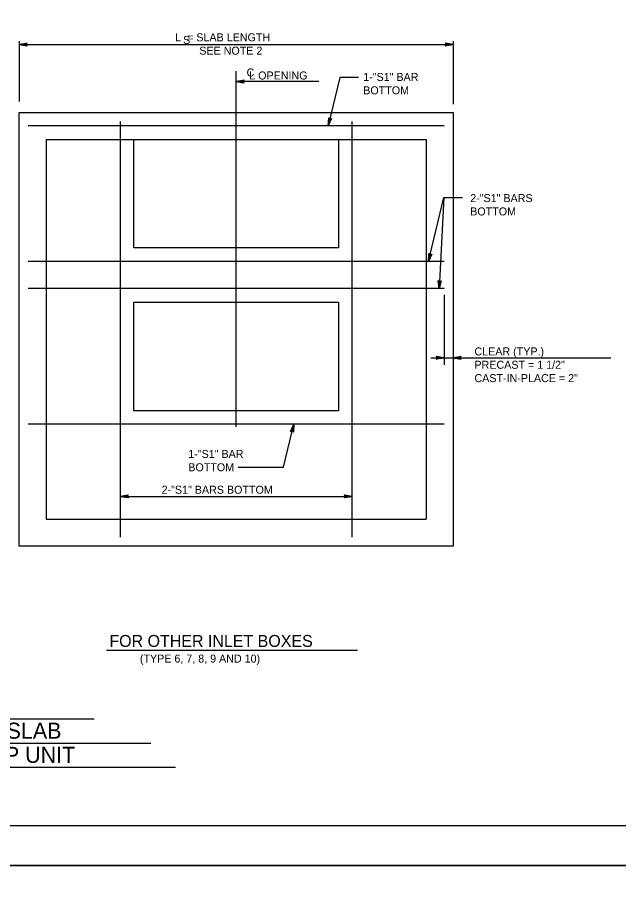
# Model space of a CAD drawing. Extents: x -6420 to 49575, y -4552 to 11624.
# Drawn here: x 3012 to 3751, y 7702 to 8769 of the extents above; entities that cross this region are included whole.
import ezdxf

# ---------------------------------------------------------------- set-up
doc = ezdxf.new("R2010")
doc.units = 0
doc.layers.add('1', color=7, linetype='Continuous')
doc.layers.add('PLT-BNDY', color=7, linetype='Continuous')

msp = doc.modelspace()

# ---------------------------------------------------------------- linework, layer by layer
at = {"layer": '1'}
for p, q in [((3014.2, 8739.6), (3014.2, 8665.4)), ((3014.2, 8735.5), (3547.5, 8735.5)), ((3547.5, 8739.6), (3547.5, 8662.3)), ((3280.8, 8265.5), (3280.8, 8702.9)), ((3382.3, 8690.2), (3280.8, 8690.2)), ((3408.4, 8695), (3394.1, 8635.5)), ((3431.1, 8695), (3408.4, 8695)), ((3536.4, 8635.5), (3025.3, 8635.5)), ((3138.5, 8129.9), (3138.5, 8641.1)), ((3423.2, 8129.9), (3423.2, 8641.1)), ((3047.5, 8618.8), (3047.5, 8152.2)), ((3047.5, 8618.8), (3514.2, 8618.8)), ((3155.1, 8618.8), (3406.5, 8618.8)), ((3155.1, 8485.5), (3155.1, 8618.8)), ((3406.5, 8618.8), (3406.5, 8485.5)), ((3514.2, 8618.8), (3514.2, 8152.2)), ((3517.3, 8468.8), (3536.2, 8547.4)), ((3536.2, 8547.4), (3530.4, 8435.5)), ((3536.2, 8547.4), (3558.9, 8547.4)), ((3406.5, 8485.5), (3155.1, 8485.5)), ((3536.4, 8468.8), (3025.3, 8468.8)), ((3536.4, 8435.5), (3025.3, 8435.5)), ((3536.4, 8428.1), (3536.4, 8341.8)), ((3155.1, 8418.8), (3406.5, 8418.8)), ((3155.1, 8285.5), (3155.1, 8418.8)), ((3406.5, 8418.8), (3406.5, 8285.5)), ((3520, 8350.5), (3741.2, 8350.5)), ((3406.5, 8285.5), (3155.1, 8285.5)), ((3536.4, 8268.8), (3025.3, 8268.8)), ((3338.8, 8215.9), (3351.6, 8268.8)), ((3283.4, 8215.9), (3338.8, 8215.9)), ((3138.5, 8180.2), (3423.2, 8180.2)), ((3047.5, 8152.2), (3514.2, 8152.2)), ((3121.4, 7990.9), (3429.9, 7990.9)), ((2617.2, 7906.6), (3106.4, 7906.6)), ((2548, 7876.9), (3176.1, 7876.9)), ((2514.9, 7847.2), (3206.2, 7847.2))]:
    msp.add_line(p, q, dxfattribs=at)
for points in [[(4563.9, 7775.5), (4563.9, 9625.9), (1985.1, 9625.9), (1985.1, 7775.5), (4563.9, 7775.5), (4563.9, 7862), (3907.7, 7862), (3907.7, 8074.1), (4563.9, 8074.1), (4563.9, 8169.2), (3907.7, 8169.2), (3907.7, 7775.5), (4166.3, 7775.5), (4166.3, 7862), (4166.3, 7775.5), (4418.9, 7775.5), (4418.9, 7862), (4418.9, 7821.5), (4563.9, 7821.5)], [(3014.2, 8735.5), (3023.9, 8737.3), (3023.6, 8737.1), (3023.2, 8736.8), (3023, 8736.5), (3022.8, 8736.2), (3022.7, 8735.8), (3022.7, 8735.5), (3022.7, 8735.2), (3022.8, 8734.8), (3023, 8734.5), (3023.2, 8734.2), (3023.6, 8733.9), (3023.9, 8733.7), (3014.2, 8735.5), (3023.6, 8733.9), (3023.2, 8734.2), (3014.2, 8735.5), (3023, 8734.5), (3022.8, 8734.8), (3014.2, 8735.5), (3022.7, 8735.2), (3022.7, 8735.5), (3014.2, 8735.5), (3022.7, 8735.8), (3022.8, 8736.2), (3014.2, 8735.5), (3023, 8736.5), (3023.2, 8736.8), (3014.2, 8735.5), (3023.6, 8737.1)], [(3547.5, 8735.5), (3537.7, 8733.7), (3538.1, 8733.9), (3538.5, 8734.2), (3538.7, 8734.5), (3538.8, 8734.8), (3538.9, 8735.2), (3539, 8735.5), (3538.9, 8735.8), (3538.8, 8736.2), (3538.7, 8736.5), (3538.5, 8736.8), (3538.1, 8737.1), (3537.7, 8737.3), (3547.5, 8735.5), (3538.1, 8737.1), (3538.5, 8736.8), (3547.5, 8735.5), (3538.7, 8736.5), (3538.8, 8736.2), (3547.5, 8735.5), (3538.9, 8735.8), (3539, 8735.5), (3547.5, 8735.5), (3538.9, 8735.2), (3538.8, 8734.8), (3547.5, 8735.5), (3538.7, 8734.5), (3538.5, 8734.2), (3547.5, 8735.5), (3538.1, 8733.9)], [(3280.8, 8690.2), (3290.6, 8692), (3290.2, 8691.7), (3289.9, 8691.5), (3289.7, 8691.2), (3289.5, 8690.8), (3289.4, 8690.5), (3289.4, 8690.2), (3289.4, 8689.8), (3289.5, 8689.5), (3289.7, 8689.2), (3289.9, 8688.9), (3290.2, 8688.6), (3290.6, 8688.3), (3280.8, 8690.2), (3290.2, 8688.6), (3289.9, 8688.9), (3280.8, 8690.2), (3289.7, 8689.2), (3289.5, 8689.5), (3280.8, 8690.2), (3289.4, 8689.8), (3289.4, 8690.2), (3280.8, 8690.2), (3289.4, 8690.5), (3289.5, 8690.8), (3280.8, 8690.2), (3289.7, 8691.2), (3289.9, 8691.5), (3280.8, 8690.2), (3290.2, 8691.7)], [(3394.1, 8635.5), (3394.6, 8645.4), (3394.8, 8645), (3394.9, 8644.6), (3395.2, 8644.3), (3395.5, 8644.1), (3395.8, 8643.9), (3396.1, 8643.8), (3396.4, 8643.8), (3396.8, 8643.8), (3397.1, 8643.9), (3397.5, 8644), (3397.8, 8644.3), (3398.2, 8644.6), (3394.1, 8635.5), (3397.8, 8644.3), (3397.5, 8644), (3394.1, 8635.5), (3397.1, 8643.9), (3396.8, 8643.8), (3394.1, 8635.5), (3396.4, 8643.8), (3396.1, 8643.8), (3394.1, 8635.5), (3395.8, 8643.9), (3395.5, 8644.1), (3394.1, 8635.5), (3395.2, 8644.3), (3394.9, 8644.6), (3394.1, 8635.5), (3394.8, 8645)], [(3517.3, 8468.8), (3517.8, 8478.8), (3518, 8478.4), (3518.1, 8477.9), (3518.4, 8477.7), (3518.7, 8477.4), (3519, 8477.3), (3519.3, 8477.1), (3519.6, 8477.1), (3519.9, 8477.1), (3520.3, 8477.2), (3520.7, 8477.3), (3521, 8477.6), (3521.4, 8477.9), (3517.3, 8468.8), (3521, 8477.6), (3520.7, 8477.3), (3517.3, 8468.8), (3520.3, 8477.2), (3519.9, 8477.1), (3517.3, 8468.8), (3519.6, 8477.1), (3519.3, 8477.1), (3517.3, 8468.8), (3519, 8477.3), (3518.7, 8477.4), (3517.3, 8468.8), (3518.4, 8477.7), (3518.1, 8477.9), (3517.3, 8468.8), (3518, 8478.4)], [(3530.4, 8435.5), (3529, 8445.4), (3529.3, 8445), (3529.5, 8444.6), (3529.8, 8444.4), (3530.2, 8444.2), (3530.5, 8444.1), (3530.8, 8444), (3531.1, 8444.1), (3531.5, 8444.1), (3531.8, 8444.3), (3532.2, 8444.5), (3532.4, 8444.8), (3532.7, 8445.2), (3530.4, 8435.5), (3532.4, 8444.8), (3532.2, 8444.5), (3530.4, 8435.5), (3531.8, 8444.3), (3531.5, 8444.1), (3530.4, 8435.5), (3531.1, 8444.1), (3530.8, 8444), (3530.4, 8435.5), (3530.5, 8444.1), (3530.2, 8444.2), (3530.4, 8435.5), (3529.8, 8444.4), (3529.5, 8444.6), (3530.4, 8435.5), (3529.3, 8445)], [(3536.4, 8350.5), (3526.6, 8348.7), (3527, 8349), (3527.3, 8349.2), (3527.5, 8349.5), (3527.7, 8349.9), (3527.8, 8350.2), (3527.8, 8350.5), (3527.8, 8350.9), (3527.7, 8351.2), (3527.5, 8351.5), (3527.3, 8351.8), (3527, 8352.1), (3526.6, 8352.4), (3536.4, 8350.5), (3527, 8352.1), (3527.3, 8351.8), (3536.4, 8350.5), (3527.5, 8351.5), (3527.7, 8351.2), (3536.4, 8350.5), (3527.8, 8350.9), (3527.8, 8350.5), (3536.4, 8350.5), (3527.8, 8350.2), (3527.7, 8349.9), (3536.4, 8350.5), (3527.5, 8349.5), (3527.3, 8349.2), (3536.4, 8350.5), (3527, 8349)], [(3547.5, 8350.5), (3557.3, 8352.4), (3556.9, 8352.1), (3556.5, 8351.8), (3556.3, 8351.5), (3556.1, 8351.2), (3556.1, 8350.9), (3556, 8350.5), (3556.1, 8350.2), (3556.1, 8349.9), (3556.3, 8349.5), (3556.5, 8349.2), (3556.9, 8349), (3557.3, 8348.7), (3547.5, 8350.5), (3556.9, 8349), (3556.5, 8349.2), (3547.5, 8350.5), (3556.3, 8349.5), (3556.1, 8349.9), (3547.5, 8350.5), (3556.1, 8350.2), (3556, 8350.5), (3547.5, 8350.5), (3556.1, 8350.9), (3556.1, 8351.2), (3547.5, 8350.5), (3556.3, 8351.5), (3556.5, 8351.8), (3547.5, 8350.5), (3556.9, 8352.1)], [(3351.6, 8268.8), (3351.1, 8258.9), (3350.9, 8259.3), (3350.7, 8259.7), (3350.5, 8260), (3350.2, 8260.3), (3349.9, 8260.4), (3349.6, 8260.5), (3349.2, 8260.6), (3348.9, 8260.6), (3348.6, 8260.5), (3348.2, 8260.4), (3347.8, 8260.1), (3347.5, 8259.7), (3351.6, 8268.8), (3347.8, 8260.1), (3348.2, 8260.4), (3351.6, 8268.8), (3348.6, 8260.5), (3348.9, 8260.6), (3351.6, 8268.8), (3349.2, 8260.6), (3349.6, 8260.5), (3351.6, 8268.8), (3349.9, 8260.4), (3350.2, 8260.3), (3351.6, 8268.8), (3350.5, 8260), (3350.7, 8259.7), (3351.6, 8268.8), (3350.9, 8259.3)], [(3138.5, 8180.2), (3148.2, 8182), (3147.9, 8181.7), (3147.5, 8181.5), (3147.3, 8181.1), (3147.1, 8180.8), (3147, 8180.5), (3147, 8180.2), (3147, 8179.8), (3147.1, 8179.5), (3147.3, 8179.2), (3147.5, 8178.9), (3147.9, 8178.6), (3148.2, 8178.3), (3138.5, 8180.2), (3147.9, 8178.6), (3147.5, 8178.9), (3138.5, 8180.2), (3147.3, 8179.2), (3147.1, 8179.5), (3138.5, 8180.2), (3147, 8179.8), (3147, 8180.2), (3138.5, 8180.2), (3147, 8180.5), (3147.1, 8180.8), (3138.5, 8180.2), (3147.3, 8181.1), (3147.5, 8181.5), (3138.5, 8180.2), (3147.9, 8181.7)], [(3423.2, 8180.2), (3413.4, 8178.3), (3413.8, 8178.6), (3414.2, 8178.9), (3414.3, 8179.2), (3414.5, 8179.5), (3414.6, 8179.8), (3414.7, 8180.2), (3414.6, 8180.5), (3414.5, 8180.8), (3414.3, 8181.1), (3414.2, 8181.5), (3413.8, 8181.7), (3413.4, 8182), (3423.2, 8180.2), (3413.8, 8181.7), (3414.2, 8181.5), (3423.2, 8180.2), (3414.3, 8181.1), (3414.5, 8180.8), (3423.2, 8180.2), (3414.6, 8180.5), (3414.7, 8180.2), (3423.2, 8180.2), (3414.6, 8179.8), (3414.5, 8179.5), (3423.2, 8180.2), (3414.3, 8179.2), (3414.2, 8178.9), (3423.2, 8180.2), (3413.8, 8178.6)]]:
    msp.add_lwpolyline(points, dxfattribs=at)
msp.add_lwpolyline([(3014.2, 8652.2), (3547.5, 8652.2), (3547.5, 8118.8), (3014.2, 8118.8)], close=True, dxfattribs=at)
at = {"layer": 'PLT-BNDY'}
for points in [[(1857.2, 9675.1), (4616.4, 9675.1), (4616.4, 7726.3), (1857.2, 7726.3)], [(1857.2, 7726.3), (4616.4, 7726.3), (4616.4, 5777.4), (1857.2, 5777.4)]]:
    msp.add_lwpolyline(points, close=True, dxfattribs=at)

# ---------------------------------------------------------------- texts
at = {"layer": '1'}
for s, height, p in [('L  = SLAB LENGTH', 9.843, (3205.9, 8739.5)), ('S', 9.84, (3215.6, 8736.3)), ('SEE NOTE 2', 9.84, (3235.5, 8723.1)), ('C', 9.84, (3293.6, 8696.3)), ('L OPENING', 9.84, (3296.9, 8692.6)), ('1-"S1" BAR', 9.84, (3437, 8690.8)), ('BOTTOM', 9.84, (3437, 8674.4)), ('2-"S1" BARS', 9.843, (3568.5, 8541.9)), ('BOTTOM', 9.84, (3568.5, 8525.5)), ('CLEAR (TYP.)', 9.843, (3573.7, 8353.4)), ('PRECAST = 1 1/2"', 9.843, (3573.7, 8337)), ('CAST-IN-PLACE = 2"', 9.843, (3573.7, 8320.6)), ('1-"S1" BAR', 9.84, (3222, 8227.4)), ('BOTTOM', 9.84, (3222, 8211)), ('2-"S1" BARS BOTTOM', 9.843, (3189.2, 8183.4)), ('FOR OTHER INLET BOXES', 14.69, (3125, 7995.1)), ('(TYPE 6, 7, 8, 9 AND 10)', 9.843, (3162.5, 7975.8)), ('RECTANGULAR OPENINGS IN TOP SLAB', 19.685, (2551.2, 7882.3)), ('FOR DOUBLE TYPE M CONCRETE TOP UNIT', 19.685, (2521.3, 7852.6))]:
    msp.add_text(s, height=height, dxfattribs=at).set_placement(p)

doc.saveas('drawing.dxf')
